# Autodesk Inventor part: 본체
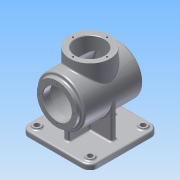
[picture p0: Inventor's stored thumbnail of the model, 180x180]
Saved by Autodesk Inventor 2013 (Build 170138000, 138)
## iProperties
Created: 2015-07
Part Number: 본체
Material: 알루미늄 6061
Document SubType Name: Modeling
Designer: Administrator
Density: 2.71 g/cm^3
Mass: 1276.08 g
Surface Area: 1271.73 cm^2
Volume: 470.878 cm^3
Author: Administrator
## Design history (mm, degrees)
sketch "스케치1"
  geometry: C1 r 45 at (0, 0); 1 further point
  constraints: 1 centre point, 1 coincident
  dimensions: "d0" = 90 diameter of C1
extrude "돌출1" new body sketch "스케치1" stored distance "d2" = 110; taper "d3" = 0 deg
sketch "스케치3"
  geometry: C1 r 38 at (0, 0); 1 further point
  constraints: 1 centre point, 1 coincident
  dimensions: "d162" = 76 diameter of C1
extrude "돌출2" join sketch "스케치3" distance "d6" = 62; taper "d7" = 0 deg
node "작업 평면1"
sketch "스케치4"
  geometry: L1 (-50, 65)-(50, 65); L2 (65, 50)-(65, -50); L3 (50, -65)-(-50, -65); L4 (-65, -50)-(-65, 50); A1 r 15 centre (-50, 50) between (-50, 65) and (-65, 50); A2 r 15 centre (-50, -50) between (-65, -50) and (-50, -65); A3 r 15 centre (50, -50) between (50, -65) and (65, -50); A4 r 15 centre (50, 50) between (65, 50) and (50, 65); 3 further points
  constraints: 8 end point, 8 point on circle, 8 tangent, 4 centre point, 3 equal radius, 2 midpoint, 2 parallel, 2 perpendicular, 1 horizontal, 1 horizontal alignment, 1 vertical alignment
  dimensions: "d9" = 130 distance between parallel lines of L4 L2; "d11" = 15 radius of A1
extrude "돌출3" join sketch "스케치4" distance "d12" = 10; taper "d13" = 0 deg
sketch "스케치5"
  geometry: L1 (45, 55)-(-45, 55) reference; L2 (-45, -55)-(-45, 55) reference; L3 (45, -55)-(45, 55) reference; L4 (-45, -55)-(45, -55) reference; L5 (-5, 45)-(5, 45); L6 (5, 45)-(5, -45); L7 (5, -45)-(-5, -45); L8 (-5, -45)-(-5, 45); L9 (-45, 5)-(45, 5); L10 (45, 5)-(45, -5); L11 (45, -5)-(-45, -5); L12 (-45, -5)-(-45, 5); 6 further points
  constraints: 16 end point, 5 midpoint, 4 parallel, 2 horizontal, 2 horizontal alignment, 2 perpendicular, 2 vertical alignment
  dimensions: "d14" = 90 distance between parallel lines of L7 L5; "d16" = 10 distance between parallel lines of L8 L6; "d17" = 10 distance between parallel lines of L11 L9; "d18" = 90 distance between parallel lines of L12 L10
extrude "돌출4" join sketch "스케치5" distance "d19" = 78; taper "d20" = 0 deg
sketch "스케치6"
  geometry: L1 (-45, -55)-(45, -55) reference; L2 (0, -48)-(0, 48); L3 (0, -48)-(40, -48); L4 (40, -48)-(40, 48); L5 (40, 48)-(0, 48); 2 further points
  constraints: 8 end point, 3 perpendicular, 1 midpoint, 1 parallel, 1 point on line
  dimensions: "d30" = 96 distance of L2.start L2.end; "d32" = 7 distance between parallel lines of L3 L1; "d33" = 80 diameter of L4 L2
revolve "회전1" sketch "스케치6" stored, may be unused: angle "d34" = 90 deg
sketch "스케치9"
  geometry: C1 r 7.5 at (-50, 50); C2 r 7.5 at (50, 50); C3 r 7.5 at (50, -50); C4 r 7.5 at (-50, -50); 1 further point
  constraints: 4 centre point, 3 equal radius, 2 horizontal alignment, 2 vertical alignment
  dimensions: "d62" = 100 distance of C1.centre C2.centre; "d64" = 50 horizontal distance of point (0, 0) C2.centre; "d65" = 100 distance of C3.centre C2.centre; "d66" = 50 horizontal distance of point (0, 0) C3.centre; "d67" = 15 diameter of C2
extrude "돌출6" join sketch "스케치9" distance "d68" = 3; taper "d69" = 0 deg
hole "구멍4" diameter "d72" = 10; stored, may be unused: countersink angle "d76" = 90 deg, drill point angle "d78" = 0 deg; dims "d70" = 10, "d71" = 10, "d73" = 6, "d74" = 54, "d75" = 14, "d77" = 14
hole "구멍5" diameter "d81" = 10; stored, may be unused: countersink angle "d85" = 90 deg, drill point angle "d87" = 0 deg; dims "d79" = 10, "d80" = 10, "d82" = 6, "d83" = 54, "d84" = 14, "d86" = 14
hole "구멍6" diameter "d90" = 10; stored, may be unused: countersink angle "d94" = 90 deg, drill point angle "d96" = 0 deg; dims "d88" = 10, "d89" = 10, "d91" = 6, "d92" = 54, "d93" = 14, "d95" = 14
hole "구멍7" diameter "d99" = 10; stored, may be unused: countersink angle "d103" = 90 deg, drill point angle "d105" = 0 deg; dims "d97" = 10, "d98" = 10, "d100" = 6, "d101" = 54, "d102" = 14, "d104" = 14
sketch "스케치10"
  geometry: C1 r 38 at (0, 0); 1 further point
  constraints: 1 centre point, 1 coincident
  dimensions: "d106" = 76 diameter of C1
extrude "돌출7" join sketch "스케치10" distance "d108" = 7; taper "d109" = 0 deg
hole "구멍8" diameter "d112" = 54; stored, may be unused: countersink angle "d116" = 90 deg, drill point angle "d118" = 0 deg; dims "d110" = 10, "d111" = 10, "d113" = 6, "d114" = 54, "d115" = 14, "d117" = 14
sketch "스케치11"
  geometry: A1 r 32 centre (0, 0) between (0, 32) and (0, -32); 3 further points
  constraints: 4 point on circle, 2 horizontal alignment, 2 vertical alignment, 1 centre point, 1 coincident
  dimensions: "d119" = 64 diameter of A1
hole "구멍9" sketch "스케치11" at (0, 32), (0, -32), (32, 0), (-32, 0) diameter "d121" = 3.242; stored, may be unused: countersink angle "d125" = 90 deg, drill point angle "d127" = 118 deg; dims "d122" = 8, "d123" = 54, "d124" = 14, "d126" = 10
sketch "스케치13"
  geometry: L1 (-24.887, 3.602)-(24.887, 3.602); L2 (24.887, 3.602)-(24.887, -3.602); L3 (24.887, -3.602)-(-24.887, -3.602); L4 (-24.887, -3.602)-(-24.887, 3.602); 6 further points
  constraints: 4 midpoint, 2 horizontal alignment, 2 vertical alignment, 1 coincident, 2 other
  dimensions: "d137" = 49.77477 distance between parallel lines of L2 L4; "d138" = 7.20489 distance between parallel lines of L3 L1
feature "엠보싱1" sketch "스케치13" dims "d2" = 110, "d139" = 0.5, "d140" = 0
fillet "모깎기1" dims "d141" = 3
fillet "모깎기2" dims "d142" = 3
fillet "모깎기4" dims "d144" = 3
fillet "모깎기5" dims "d145" = 3
fillet "모깎기7" dims "d147" = 3
fillet "모깎기8" dims "d151" = 3
fillet "모깎기9" dims "d152" = 3
fillet "모깎기10" dims "d153" = 3
chamfer "모따기2" distance "d154" = 1; stored, may be unused: second distance "d155" = 2, angle "d156" = 45 deg
hole "구멍11" diameter "d167" = 54; stored, may be unused: countersink angle "d171" = 90 deg, drill point angle "d173" = 0 deg; dims "d165" = 10, "d166" = 10, "d168" = 6, "d169" = 4, "d170" = 2, "d172" = 50
sketch "스케치14"
  geometry: A1 r 32 centre (0, 0) between (0, 32) and (0, -32); 3 further points
  constraints: 4 point on circle, 2 horizontal alignment, 2 vertical alignment, 1 centre point, 1 coincident
  dimensions: "d176" = 64 diameter of A1
hole "구멍12" sketch "스케치14" at (0, 32), (0, -32), (32, 0), (-32, 0) diameter "d178" = 3.242; stored, may be unused: countersink angle "d182" = 90 deg, drill point angle "d184" = 118 deg; dims "d179" = 8, "d180" = 4, "d181" = 2, "d183" = 10
chamfer "모따기4" distance "d185" = 1; stored, may be unused: second distance "d186" = 2, angle "d187" = 45 deg
fillet "모깎기11" dims "d188" = 3
fillet "모깎기12" dims "d189" = 3
node "솔리드1"
